Omron CX-Programmer project NewProject (CX-Programmer 6.11)

# PLC Elevator: CPM1(CPM1A) CPU20

## Global symbols (name address type ; comment)
210.01 BOOL  ; Manual Up
210.02 BOOL  ; Manual Down
Button_1 200.07 BOOL  ; Call Button 1st
Button_2 200.06 BOOL  ; Call Button 2nd
Button_3 200.05 BOOL  ; Call Button 3rd
Button_4 200.04 BOOL  ; Call Button 4th
Button_Dn 200.09 BOOL  ; Manual Down
Button_Up 200.08 BOOL  ; Manual Up
Floor_Number 220 CHANNEL  ; Current Floor Number
I_00 0.00 BOOL  ; GN Start - 4th
I_01 0.01 BOOL  ; BK Start - 3rd
I_02 0.02 BOOL  ; BK Jog - 2nd
I_03 0.03 BOOL  ; RD EStop - 1st
I_04 0.04 BOOL  ; RD Stop - UP
I_05 0.05 BOOL  ; RD Stop - DN
I_07 0.07 BOOL  ; Basement
I_08 0.08 BOOL  ; Level 1
I_09 0.09 BOOL  ; Level 4
I_10 0.10 BOOL  ; Level 3
I_11 0.11 BOOL  ; Level 2
LS_Basement 200.10 BOOL  ; Elevator @ Basement
LS_Level1 200.00 BOOL  ; Elevator @ Level 1
LS_Level2 200.01 BOOL  ; Elevator @ Level 2
LS_Level3 200.02 BOOL  ; Elevator @ Level 3
LS_Level4 200.03 BOOL  ; Elevator @ Level 4
O_01 10.01 BOOL  ; Up Motor
O_02 10.02 BOOL  ; Down Motor
Run_Motor_Down 211.00 BOOL  ; Run Down Motor
S_02 202.00 BOOL  ; Step S02
S_03A 202.01 BOOL  ; Step S03A
S_03B 202.02 BOOL  ; Step S03B
S_03C 202.03 BOOL  ; Step S03C
S_03D 202.04 BOOL  ; Step S03D
S_03E 202.05 BOOL  ; Step S03E
S_10 202.06 BOOL  ; Step S10
T_00 201.00 BOOL  ; Transition T00
T_02A 201.01 BOOL  ; Transition T02A
T_02B 201.02 BOOL  ; Transition T02B
T_02C 201.03 BOOL  ; Transition T02C
T_02D 201.04 BOOL  ; Transition T02D
T_02E 201.05 BOOL  ; Transition T02E
T_02F 201.06 BOOL  ; Transition T02F
T_03A 201.07 BOOL  ; Transition T03A
T_03B 201.08 BOOL  ; Transition T03B
T_03C 201.09 BOOL  ; Transition T03C
T_03D 201.10 BOOL  ; Transition T03D
T_03E 201.11 BOOL  ; Transition T03E
T_10A 203.00 BOOL  ; Transition T10A
T_10B 203.01 BOOL  ; Transition T10B
T_10C 203.02 BOOL  ; Transition T10C
T_11A 203.03 BOOL  ; Transition T11A
T_11B 203.04 BOOL  ; Transition T11B
T_12A 203.05 BOOL  ; Transition T12A
T_12B 203.06 BOOL  ; Transition T12B
T_13 203.07 BOOL  ; Transition T13
T_15A 203.08 BOOL  ; Transition T15A
T_15B 203.09 BOOL  ; Transition T15B
T_16 203.10 BOOL  ; Transition T16
T_20A 205.00 BOOL  ; Transition T20A
T_20B 205.01 BOOL  ; Transition T20B
T_20C 205.02 BOOL  ; Transition T20C
T_20D 205.03 BOOL  ; Transition T20D
T_20E 205.04 BOOL  ; Transition T20E
T_30A 205.05 BOOL  ; Transition T30A
T_30B 205.06 BOOL  ; Transition T30B
T_30C 205.07 BOOL  ; Transition T30C
T_30D 205.08 BOOL  ; Transition T30D
T_30E 205.09 BOOL  ; Transition T30E
Timer_Flt_Dn TIM003 BOOL  ; Motor Down Fault
Timer_Flt_Init TIM001 BOOL  ; Initialization Fault Timer
Timer_Flt_Man_Down TIM006 BOOL  ; Manual Down Fault
Timer_Flt_Man_Up TIM004 BOOL  ; Manual Up Fault
Timer_Flt_Up TIM002 BOOL  ; Motor Up Fault
Timer_Running20 TIM005 BOOL  ; Running Timer (S20)
Timer_Running30 TIM007 BOOL  ; Running Timer (S30)

## Program Elevator (no task)

### Section Transistions

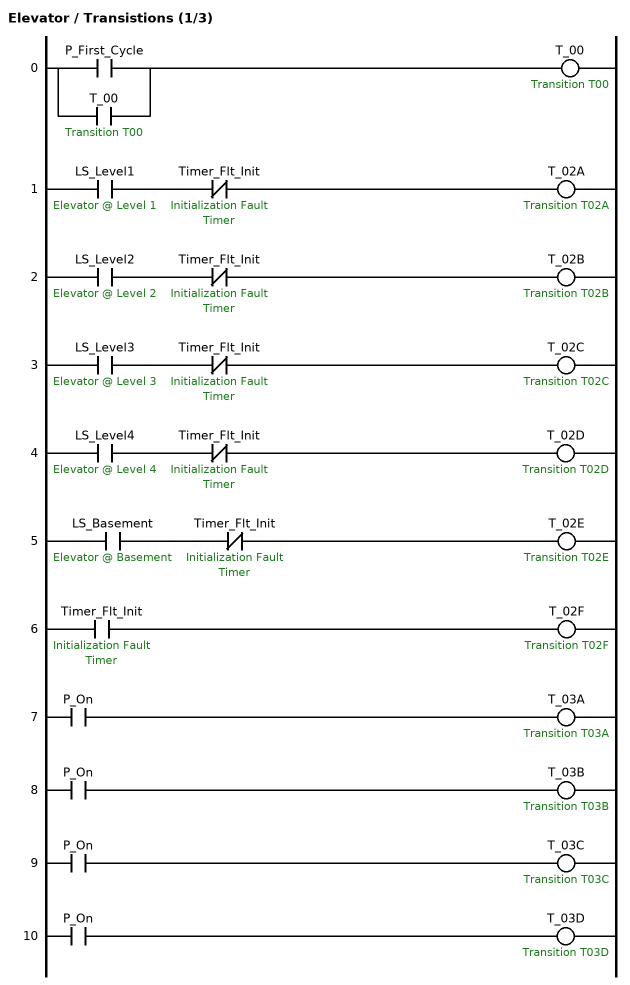
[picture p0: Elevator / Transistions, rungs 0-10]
; rung 0
LD P_First_Cycle
OR T_00  ; Transition T00
OUT T_00  ; Transition T00
; rung 1
LD LS_Level1  ; Elevator @ Level 1
ANDNOT Timer_Flt_Init  ; Initialization Fault Timer
OUT T_02A  ; Transition T02A
; rung 2
LD LS_Level2  ; Elevator @ Level 2
ANDNOT Timer_Flt_Init  ; Initialization Fault Timer
OUT T_02B  ; Transition T02B
; rung 3
LD LS_Level3  ; Elevator @ Level 3
ANDNOT Timer_Flt_Init  ; Initialization Fault Timer
OUT T_02C  ; Transition T02C
; rung 4
LD LS_Level4  ; Elevator @ Level 4
ANDNOT Timer_Flt_Init  ; Initialization Fault Timer
OUT T_02D  ; Transition T02D
; rung 5
LD LS_Basement  ; Elevator @ Basement
ANDNOT Timer_Flt_Init  ; Initialization Fault Timer
OUT T_02E  ; Transition T02E
; rung 6
LD Timer_Flt_Init  ; Initialization Fault Timer
OUT T_02F  ; Transition T02F
; rung 7
LD P_On
OUT T_03A  ; Transition T03A
; rung 8
LD P_On
OUT T_03B  ; Transition T03B
; rung 9
LD P_On
OUT T_03C  ; Transition T03C
; rung 10
LD P_On
OUT T_03D  ; Transition T03D

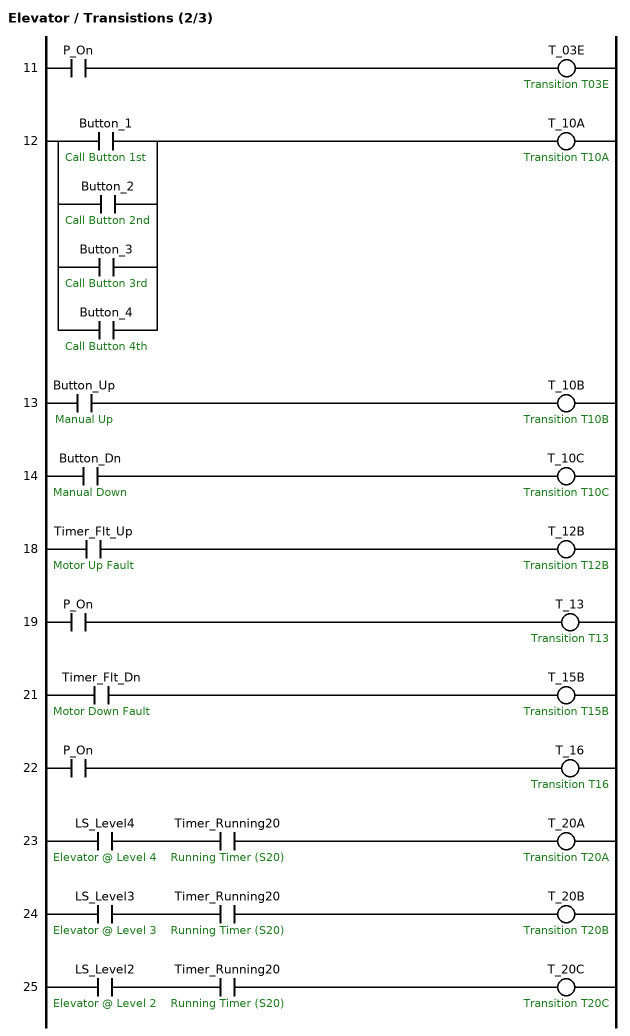
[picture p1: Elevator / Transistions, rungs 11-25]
; rung 11
LD P_On
OUT T_03E  ; Transition T03E
; rung 12
LD Button_1  ; Call Button 1st
OR Button_2  ; Call Button 2nd
OR Button_3  ; Call Button 3rd
OR Button_4  ; Call Button 4th
OUT T_10A  ; Transition T10A
; rung 13
LD Button_Up  ; Manual Up
OUT T_10B  ; Transition T10B
; rung 14
LD Button_Dn  ; Manual Down
OUT T_10C  ; Transition T10C
; rung 15
; cells of this rung as drawn
  row 0 col 6: OUT T_11A
  vertical links (row, left of col): 
; rung 16
; cells of this rung as drawn
  row 0 col 6: OUT T_11B
  vertical links (row, left of col): 
; rung 17
; cells of this rung as drawn
  row 0 col 6: OUT T_12A
  vertical links (row, left of col): 
; rung 18
LD Timer_Flt_Up  ; Motor Up Fault
OUT T_12B  ; Transition T12B
; rung 19
LD P_On
OUT T_13  ; Transition T13
; rung 20
; cells of this rung as drawn
  row 0 col 6: OUT T_15A
  vertical links (row, left of col): 
; rung 21
LD Timer_Flt_Dn  ; Motor Down Fault
OUT T_15B  ; Transition T15B
; rung 22
LD P_On
OUT T_16  ; Transition T16
; rung 23
LD LS_Level4  ; Elevator @ Level 4
AND Timer_Running20  ; Running Timer (S20)
OUT T_20A  ; Transition T20A
; rung 24
LD LS_Level3  ; Elevator @ Level 3
AND Timer_Running20  ; Running Timer (S20)
OUT T_20B  ; Transition T20B
; rung 25
LD LS_Level2  ; Elevator @ Level 2
AND Timer_Running20  ; Running Timer (S20)
OUT T_20C  ; Transition T20C

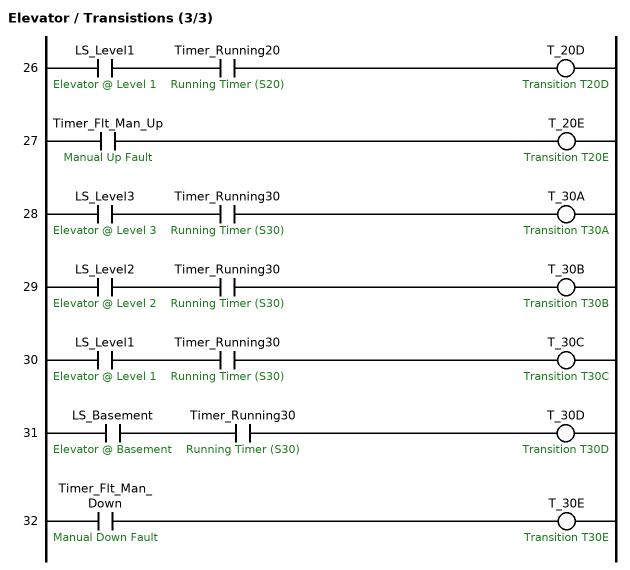
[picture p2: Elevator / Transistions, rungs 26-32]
; rung 26
LD LS_Level1  ; Elevator @ Level 1
AND Timer_Running20  ; Running Timer (S20)
OUT T_20D  ; Transition T20D
; rung 27
LD Timer_Flt_Man_Up  ; Manual Up Fault
OUT T_20E  ; Transition T20E
; rung 28
LD LS_Level3  ; Elevator @ Level 3
AND Timer_Running30  ; Running Timer (S30)
OUT T_30A  ; Transition T30A
; rung 29
LD LS_Level2  ; Elevator @ Level 2
AND Timer_Running30  ; Running Timer (S30)
OUT T_30B  ; Transition T30B
; rung 30
LD LS_Level1  ; Elevator @ Level 1
AND Timer_Running30  ; Running Timer (S30)
OUT T_30C  ; Transition T30C
; rung 31
LD LS_Basement  ; Elevator @ Basement
AND Timer_Running30  ; Running Timer (S30)
OUT T_30D  ; Transition T30D
; rung 32
LD Timer_Flt_Man_Down  ; Manual Down Fault
OUT T_30E  ; Transition T30E

### Section StepIterator

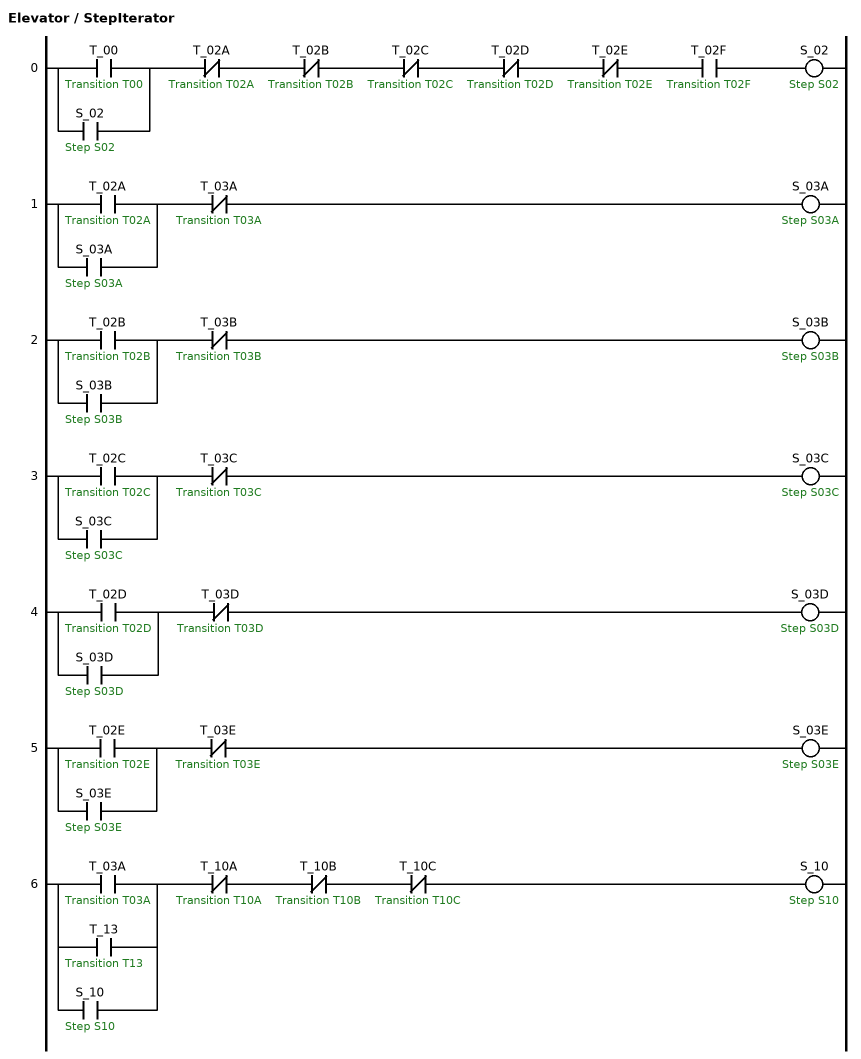
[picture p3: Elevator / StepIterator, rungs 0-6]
; rung 0
LD T_00  ; Transition T00
OR S_02  ; Step S02
ANDNOT T_02A  ; Transition T02A
ANDNOT T_02B  ; Transition T02B
ANDNOT T_02C  ; Transition T02C
ANDNOT T_02D  ; Transition T02D
ANDNOT T_02E  ; Transition T02E
AND T_02F  ; Transition T02F
OUT S_02  ; Step S02
; rung 1
LD T_02A  ; Transition T02A
OR S_03A  ; Step S03A
ANDNOT T_03A  ; Transition T03A
OUT S_03A  ; Step S03A
; rung 2
LD T_02B  ; Transition T02B
OR S_03B  ; Step S03B
ANDNOT T_03B  ; Transition T03B
OUT S_03B  ; Step S03B
; rung 3
LD T_02C  ; Transition T02C
OR S_03C  ; Step S03C
ANDNOT T_03C  ; Transition T03C
OUT S_03C  ; Step S03C
; rung 4
LD T_02D  ; Transition T02D
OR S_03D  ; Step S03D
ANDNOT T_03D  ; Transition T03D
OUT S_03D  ; Step S03D
; rung 5
LD T_02E  ; Transition T02E
OR S_03E  ; Step S03E
ANDNOT T_03E  ; Transition T03E
OUT S_03E  ; Step S03E
; rung 6
LD T_03A  ; Transition T03A
OR T_13  ; Transition T13
OR S_10  ; Step S10
ANDNOT T_10A  ; Transition T10A
ANDNOT T_10B  ; Transition T10B
ANDNOT T_10C  ; Transition T10C
OUT S_10  ; Step S10

### Section Steps

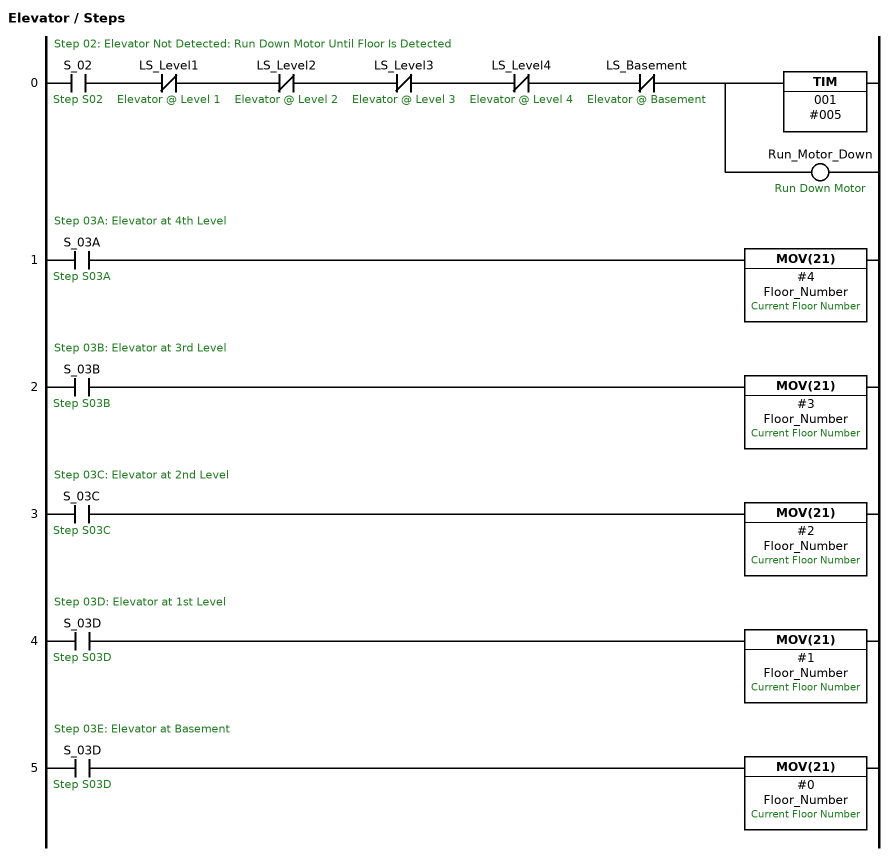
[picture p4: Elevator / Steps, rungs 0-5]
; rung 0: Step 02: Elevator Not Detected: Run Down Motor Until Floor Is Detected
LD S_02  ; Step S02
ANDNOT LS_Level1  ; Elevator @ Level 1
ANDNOT LS_Level2  ; Elevator @ Level 2
ANDNOT LS_Level3  ; Elevator @ Level 3
ANDNOT LS_Level4  ; Elevator @ Level 4
ANDNOT LS_Basement  ; Elevator @ Basement
TIM 001 #005
OUT Run_Motor_Down  ; Run Down Motor
; rung 1: Step 03A: Elevator at 4th Level
LD S_03A  ; Step S03A
MOV(21) #4 Floor_Number  ; Current Floor Number
; rung 2: Step 03B: Elevator at 3rd Level
LD S_03B  ; Step S03B
MOV(21) #3 Floor_Number  ; Current Floor Number
; rung 3: Step 03C: Elevator at 2nd Level
LD S_03C  ; Step S03C
MOV(21) #2 Floor_Number  ; Current Floor Number
; rung 4: Step 03D: Elevator at 1st Level
LD S_03D  ; Step S03D
MOV(21) #1 Floor_Number  ; Current Floor Number
; rung 5: Step 03E: Elevator at Basement
LD S_03D  ; Step S03D
MOV(21) #0 Floor_Number  ; Current Floor Number
; rung 6: Step 10: Wait for Call

### Section IO
; rung 1: Inputs

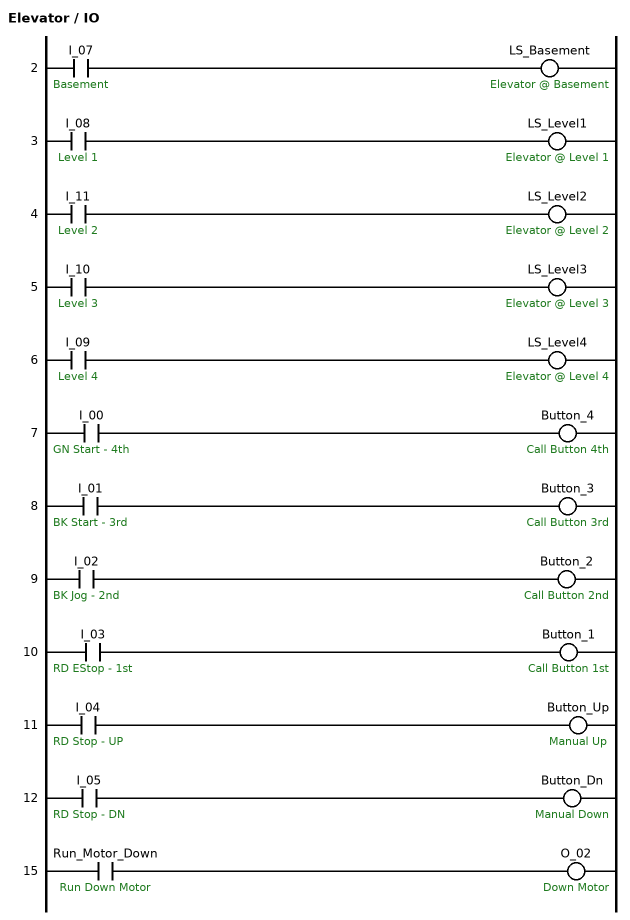
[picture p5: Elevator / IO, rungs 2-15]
; rung 2
LD I_07  ; Basement
OUT LS_Basement  ; Elevator @ Basement
; rung 3
LD I_08  ; Level 1
OUT LS_Level1  ; Elevator @ Level 1
; rung 4
LD I_11  ; Level 2
OUT LS_Level2  ; Elevator @ Level 2
; rung 5
LD I_10  ; Level 3
OUT LS_Level3  ; Elevator @ Level 3
; rung 6
LD I_09  ; Level 4
OUT LS_Level4  ; Elevator @ Level 4
; rung 7
LD I_00  ; GN Start - 4th
OUT Button_4  ; Call Button 4th
; rung 8
LD I_01  ; BK Start - 3rd
OUT Button_3  ; Call Button 3rd
; rung 9
LD I_02  ; BK Jog - 2nd
OUT Button_2  ; Call Button 2nd
; rung 10
LD I_03  ; RD EStop - 1st
OUT Button_1  ; Call Button 1st
; rung 11
LD I_04  ; RD Stop - UP
OUT Button_Up  ; Manual Up
; rung 12
LD I_05  ; RD Stop - DN
OUT Button_Dn  ; Manual Down
; rung 14: Outputs
; rung 15
LD Run_Motor_Down  ; Run Down Motor
OUT O_02  ; Down Motor

### Section Section1
; rung 0
END(01)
